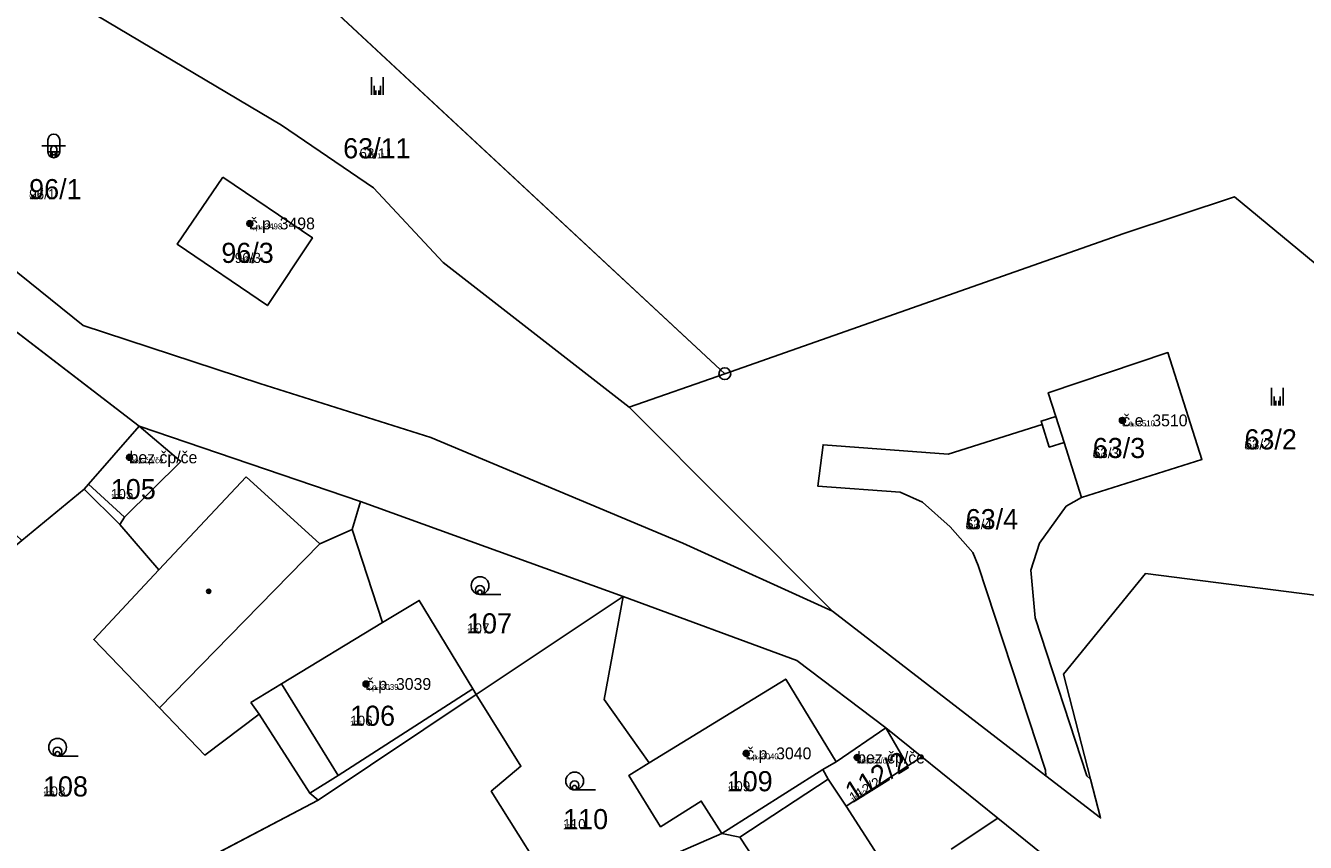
# Model space of a CAD drawing. Extents: x -759873 to -758487, y -975024 to -973516.
# Drawn here: x -759433 to -759325, y -974277 to -974208 of the extents above; entities that cross this region are included whole.
import ezdxf

# ---------------------------------------------------------------- set-up
doc = ezdxf.new("R2010")
doc.units = 0
for name, color, linetype in [('KAT_02_hranice parcel', 7, 'Continuous'), ('KAT_03_1000_st čísla parcelní', 7, 'Continuous'), ('KAT_03_1000_čísla parcelní', 7, 'Continuous'), ('KAT_03_1000_čísla popisná', 7, 'Continuous'), ('KAT_03_250_st čísla parcelní', 7, 'Continuous'), ('KAT_03_250_čísla parcelní', 7, 'Continuous'), ('KAT_03_250_čísla popisná', 7, 'Continuous'), ('KAT_03_500_st čísla parcelní', 7, 'Continuous'), ('KAT_03_500_čísla parcelní', 7, 'Continuous'), ('KAT_03_500_čísla popisná', 7, 'Continuous'), ('KAT_04_vnitřní kresba', 7, 'Continuous'), ('KAT_05_1000_značky kultur', 7, 'Continuous'), ('KAT_05_250_značky kultur', 7, 'Continuous'), ('KAT_05_500_značky kultur', 7, 'Continuous'), ('KAT_07_1000_značky budov', 7, 'Continuous'), ('KAT_07_250_značky budov', 7, 'Continuous'), ('KAT_07_500_značky budov', 7, 'Continuous'), ('KAT_11_značky bodu BP', 7, 'Continuous'), ('KAT_14_plocha_budovy', 7, 'Continuous'), ('KAT_14_plocha_pozemek', 7, 'Continuous')]:
    doc.layers.add(name, color=color, linetype=linetype)

msp = doc.modelspace()

# ---------------------------------------------------------------- linework, layer by layer
at = {"layer": 'KAT_02_hranice parcel'}
for p, q in [((-759416.57, -974197.82), (-759373.99, -974237.42)), ((-759453.16, -974219.06), (-759423.45, -974241.84)), ((-759373.99, -974237.42), (-759382.06, -974240.25)), ((-759382.06, -974240.25), (-759364.9, -974257.48)), ((-759423.45, -974241.84), (-759404.76, -974248.21)), ((-759433.37, -974251.51), (-759428.09, -974247.17)), ((-759428.09, -974247.17), (-759425.09, -974250.16)), ((-759404.76, -974248.21), (-759382.57, -974256.23)), ((-759394.98, -974264.51), (-759382.57, -974256.23)), ((-759364.9, -974257.48), (-759346.87, -974271.37)), ((-759408.33, -974273.42), (-759394.98, -974264.51)), ((-759360.4, -974267.32), (-759357.36, -974269.77)), ((-759374.24, -974276.25), (-759365.72, -974270.85)), ((-759427.48, -974283.47), (-759408.33, -974273.42))]:
    msp.add_line(p, q, dxfattribs=at)
for points in [[(-759382.06, -974240.25), (-759397.78, -974228.02), (-759403.67, -974221.73), (-759411.44, -974216.42), (-759427.02, -974207.16), (-759417.13, -974198.96), (-759416.57, -974197.82)], [(-759364.9, -974257.48), (-759377.53, -974251.74), (-759398.81, -974242.81), (-759413.25, -974238.25), (-759428.19, -974233.35), (-759448.25, -974217.2)], [(-759416.37, -974220.83), (-759408.82, -974225.94), (-759412.62, -974231.67), (-759420.24, -974226.48), (-759416.37, -974220.83)], [(-759373.99, -974237.42), (-759340.28, -974225.59), (-759330.94, -974222.47), (-759318.77, -974232.53)], [(-759347.19, -974241.71), (-759347.28, -974241.42), (-759346.03, -974241.02), (-759346.67, -974239.02), (-759336.57, -974235.63), (-759333.7, -974244.65), (-759343.86, -974247.88)], [(-759346.87, -974271.37), (-759346.89, -974270.91), (-759352.58, -974253.61), (-759353.05, -974252.52), (-759354.95, -974250.36), (-759357.28, -974248.27), (-759359.17, -974247.42), (-759366.12, -974246.92), (-759365.69, -974243.42), (-759355.13, -974244.22), (-759347.19, -974241.71)], [(-759347.19, -974241.71), (-759346.59, -974243.62), (-759345.34, -974243.22), (-759343.86, -974247.88)], [(-759428.09, -974247.17), (-759427.72, -974246.75), (-759423.45, -974241.84)], [(-759425.09, -974250.16), (-759424.69, -974249.54), (-759419.94, -974244.83), (-759423.45, -974241.84)], [(-759394.98, -974264.51), (-759395.28, -974264.04), (-759399.79, -974256.56), (-759402.91, -974258.44), (-759405.47, -974250.58), (-759404.76, -974248.21)], [(-759343.86, -974247.88), (-759345.17, -974248.61), (-759347.41, -974251.72), (-759348.14, -974254.02), (-759347.78, -974258.04), (-759343.41, -974271.37), (-759343.09, -974271.67)], [(-759425.09, -974250.16), (-759421.79, -974253.98), (-759427.28, -974259.86), (-759421.73, -974265.62), (-759417.89, -974269.62), (-759413.32, -974266.17), (-759409.03, -974272.84), (-759408.33, -974273.42)], [(-759343.09, -974271.67), (-759345.37, -974262.78), (-759338.47, -974254.29), (-759324.16, -974256.13), (-759317.89, -974266.22), (-759318.14, -974285.7), (-759311.79, -974294.78), (-759308.64, -974296.79)], [(-759382.57, -974256.23), (-759384.18, -974264.92), (-759380.39, -974270.29), (-759382.09, -974271.34), (-759379.41, -974275.68), (-759375.98, -974273.51), (-759374.24, -974276.25)], [(-759382.57, -974256.23), (-759367.9, -974261.65), (-759360.4, -974267.32)], [(-759394.98, -974264.51), (-759391.21, -974270.57), (-759393.71, -974272.68), (-759387.77, -974282.14)], [(-759365.72, -974270.85), (-759364.59, -974270.19), (-759360.4, -974267.32)], [(-759357.36, -974269.77), (-759358.53, -974270.53), (-759363.73, -974273.94), (-759365.27, -974271.66), (-759365.72, -974270.85)], [(-759357.36, -974269.77), (-759350.93, -974274.95), (-759343.18, -974281.19)], [(-759346.87, -974271.37), (-759342.25, -974274.93), (-759343.09, -974271.67)], [(-759387.77, -974282.14), (-759384.06, -974280.53), (-759374.24, -974276.25)], [(-759374.24, -974276.25), (-759372.72, -974276.55), (-759368.52, -974282.94), (-759375.24, -974287.36), (-759370.69, -974296.74)]]:
    msp.add_lwpolyline(points, dxfattribs=at)
at = {"layer": 'KAT_03_1000_čísla popisná'}
for centre in [(-759414.11, -974224.73), (-759340.41, -974241.36), (-759424.26, -974244.48), (-759404.29, -974263.62), (-759372.18, -974269.48), (-759362.81, -974269.83)]:
    msp.add_circle(centre, 0.25, dxfattribs=at)
at = {"layer": 'KAT_03_250_čísla popisná'}
for centre in [(-759414.11, -974224.73), (-759340.41, -974241.36), (-759424.26, -974244.48), (-759404.29, -974263.62), (-759372.18, -974269.48), (-759362.81, -974269.83)]:
    msp.add_circle(centre, 0.0625, dxfattribs=at)
at = {"layer": 'KAT_03_500_čísla popisná'}
for centre in [(-759414.11, -974224.73), (-759340.41, -974241.36), (-759424.26, -974244.48), (-759404.29, -974263.62), (-759372.18, -974269.48), (-759362.81, -974269.83)]:
    msp.add_circle(centre, 0.125, dxfattribs=at)
at = {"layer": 'KAT_04_vnitřní kresba'}
for p, q in [((-759346.03, -974241.02), (-759345.34, -974243.22)), ((-759421.79, -974253.98), (-759414.4, -974246.13)), ((-759414.4, -974246.13), (-759408.18, -974251.78)), ((-759427.72, -974246.75), (-759424.69, -974249.54)), ((-759408.18, -974251.78), (-759405.47, -974250.58)), ((-759415.83, -974259.59), (-759408.18, -974251.78)), ((-759411.42, -974263.6), (-759402.91, -974258.44)), ((-759421.73, -974265.62), (-759415.83, -974259.59)), ((-759380.39, -974270.29), (-759368.84, -974263.21)), ((-759368.84, -974263.21), (-759364.59, -974270.19)), ((-759414.01, -974265.17), (-759411.42, -974263.6)), ((-759411.42, -974263.6), (-759406.64, -974271.34)), ((-759406.64, -974271.34), (-759395.28, -974264.04)), ((-759414.01, -974265.17), (-759413.32, -974266.17)), ((-759360.4, -974267.32), (-759358.53, -974270.53)), ((-759409.03, -974272.84), (-759406.64, -974271.34)), ((-759372.72, -974276.55), (-759365.27, -974271.66)), ((-759363.73, -974273.94), (-759361.08, -974278.05)), ((-759354.87, -974277.58), (-759350.93, -974274.95))]:
    msp.add_line(p, q, dxfattribs=at)
at = {"layer": 'KAT_05_1000_značky kultur'}
for p, q in [((-759403.84, -974213.87), (-759403.84, -974212.37)), ((-759402.84, -974213.87), (-759402.84, -974212.37)), ((-759431.16, -974217.68), (-759431.16, -974218.68)), ((-759430.16, -974218.68), (-759430.16, -974217.68)), ((-759431.66, -974218.18), (-759429.66, -974218.18)), ((-759327.83, -974240.1), (-759327.83, -974238.6)), ((-759326.83, -974240.1), (-759326.83, -974238.6)), ((-759394.66, -974256.06), (-759392.91, -974256.06)), ((-759430.34, -974269.71), (-759428.59, -974269.71)), ((-759386.67, -974272.56), (-759384.92, -974272.56))]:
    msp.add_line(p, q, dxfattribs=at)
for centre in [(-759394.66, -974255.31), (-759430.34, -974268.96), (-759386.67, -974271.81)]:
    msp.add_circle(centre, 0.75, dxfattribs=at)
for centre, start, end in [((-759430.66, -974217.68), 0, 180), ((-759430.66, -974218.68), 180, 359.9879)]:
    msp.add_arc(centre, 0.5, start, end, dxfattribs=at)
at = {"layer": 'KAT_05_250_značky kultur'}
for p, q in [((-759403.46, -974213.87), (-759403.46, -974213.49)), ((-759403.21, -974213.87), (-759403.21, -974213.49)), ((-759430.91, -974218.93), (-759430.41, -974218.93)), ((-759430.79, -974218.81), (-759430.79, -974219.06)), ((-759430.53, -974219.06), (-759430.53, -974218.81)), ((-759327.45, -974240.1), (-759327.45, -974239.72)), ((-759327.2, -974240.1), (-759327.2, -974239.72)), ((-759394.67, -974256.06), (-759394.23, -974256.06)), ((-759430.35, -974269.71), (-759429.91, -974269.71)), ((-759386.68, -974272.56), (-759386.24, -974272.56))]:
    msp.add_line(p, q, dxfattribs=at)
for centre in [(-759394.67, -974255.87), (-759430.35, -974269.52), (-759386.68, -974272.37)]:
    msp.add_circle(centre, 0.187, dxfattribs=at)
for centre, start, end in [((-759430.66, -974218.81), 0, 180), ((-759430.66, -974219.06), 180, 359.9879)]:
    msp.add_arc(centre, 0.125, start, end, dxfattribs=at)
at = {"layer": 'KAT_05_500_značky kultur'}
for p, q in [((-759403.59, -974213.87), (-759403.59, -974213.12)), ((-759403.08, -974213.87), (-759403.08, -974213.12)), ((-759431.16, -974218.68), (-759430.16, -974218.68)), ((-759430.91, -974218.43), (-759430.91, -974218.93)), ((-759430.41, -974218.93), (-759430.41, -974218.43)), ((-759327.58, -974240.1), (-759327.58, -974239.35)), ((-759327.08, -974240.1), (-759327.08, -974239.35)), ((-759394.67, -974256.06), (-759393.79, -974256.06)), ((-759430.35, -974269.71), (-759429.47, -974269.71)), ((-759386.68, -974272.56), (-759385.8, -974272.56))]:
    msp.add_line(p, q, dxfattribs=at)
for centre in [(-759394.67, -974255.68), (-759430.35, -974269.33), (-759386.68, -974272.18)]:
    msp.add_circle(centre, 0.375, dxfattribs=at)
for centre, start, end in [((-759430.66, -974218.43), 0, 180), ((-759430.66, -974218.93), 180, 359.9879)]:
    msp.add_arc(centre, 0.25, start, end, dxfattribs=at)
at = {"layer": 'KAT_07_1000_značky budov'}
for centre in [(-759414.12, -974224.73), (-759340.42, -974241.36), (-759424.27, -974244.48), (-759417.58, -974255.8), (-759404.3, -974263.62), (-759372.19, -974269.48), (-759362.82, -974269.83)]:
    msp.add_circle(centre, 0.175, dxfattribs=at)
at = {"layer": 'KAT_07_250_značky budov'}
for centre in [(-759414.11, -974224.73), (-759340.41, -974241.36), (-759424.26, -974244.48), (-759417.57, -974255.8), (-759404.29, -974263.62), (-759372.18, -974269.48), (-759362.81, -974269.83)]:
    msp.add_circle(centre, 0.0437, dxfattribs=at)
at = {"layer": 'KAT_07_500_značky budov'}
for centre in [(-759414.11, -974224.73), (-759340.41, -974241.36), (-759424.26, -974244.48), (-759417.57, -974255.8), (-759404.29, -974263.62), (-759372.18, -974269.48), (-759362.81, -974269.83)]:
    msp.add_circle(centre, 0.0875, dxfattribs=at)
at = {"layer": 'KAT_11_značky bodu BP'}
for radius in [0.5, 0.0303]:
    msp.add_circle((-759373.99, -974237.42), radius, dxfattribs=at)
at = {"layer": 'KAT_14_plocha_budovy'}
for points in [[(-759416.37, -974220.83), (-759420.24, -974226.48), (-759412.62, -974231.67), (-759408.82, -974225.94)], [(-759336.57, -974235.63), (-759346.67, -974239.02), (-759346.03, -974241.02), (-759345.34, -974243.22), (-759343.86, -974247.88), (-759333.7, -974244.65)], [(-759427.72, -974246.75), (-759424.69, -974249.54), (-759419.94, -974244.83), (-759423.45, -974241.84)], [(-759411.42, -974263.6), (-759406.64, -974271.34), (-759395.28, -974264.04), (-759399.79, -974256.56), (-759402.91, -974258.44)], [(-759382.09, -974271.34), (-759379.41, -974275.68), (-759375.98, -974273.51), (-759374.24, -974276.25), (-759365.72, -974270.85), (-759364.59, -974270.19), (-759368.84, -974263.21), (-759380.39, -974270.29)], [(-759363.73, -974273.94), (-759358.53, -974270.53), (-759360.4, -974267.32), (-759364.59, -974270.19), (-759365.72, -974270.85), (-759365.27, -974271.66)]]:
    msp.add_lwpolyline(points, close=True, dxfattribs=at)
at = {"layer": 'KAT_14_plocha_pozemek'}
for points in [[(-759397.78, -974228.02), (-759403.67, -974221.73), (-759411.44, -974216.42), (-759427.02, -974207.16), (-759417.13, -974198.96), (-759416.57, -974197.82), (-759409.11, -974182.46), (-759411.13, -974183.35), (-759411.55, -974185.84), (-759421.6, -974198.71), (-759430.32, -974203.35), (-759439.36, -974211.8), (-759441.1, -974209.74), (-759448.25, -974217.2), (-759428.19, -974233.35), (-759413.25, -974238.25), (-759398.81, -974242.81), (-759377.53, -974251.74), (-759364.9, -974257.48), (-759382.06, -974240.25)], [(-759373.99, -974237.42), (-759416.57, -974197.82), (-759417.13, -974198.96), (-759427.02, -974207.16), (-759411.44, -974216.42), (-759403.67, -974221.73), (-759397.78, -974228.02), (-759382.06, -974240.25)], [(-759428.09, -974247.17), (-759427.72, -974246.75), (-759423.45, -974241.84), (-759453.16, -974219.06), (-759463.77, -974223.21), (-759457.41, -974236.54), (-759459.8, -974239.06), (-759447, -974252), (-759442.74, -974247.8), (-759440.09, -974245.19), (-759433.37, -974251.51)], [(-759416.37, -974220.83), (-759408.82, -974225.94), (-759412.62, -974231.67), (-759420.24, -974226.48)], [(-759416.37, -974220.83), (-759420.24, -974226.48), (-759412.62, -974231.67), (-759408.82, -974225.94)], [(-759343.86, -974247.88), (-759333.7, -974244.65), (-759336.57, -974235.63), (-759346.67, -974239.02), (-759346.03, -974241.02), (-759347.28, -974241.42), (-759347.19, -974241.71), (-759346.59, -974243.62), (-759345.34, -974243.22)], [(-759342.25, -974274.93), (-759343.09, -974271.67), (-759343.41, -974271.37), (-759347.78, -974258.04), (-759348.14, -974254.02), (-759347.41, -974251.72), (-759345.17, -974248.61), (-759343.86, -974247.88), (-759345.34, -974243.22), (-759346.59, -974243.62), (-759347.19, -974241.71), (-759355.13, -974244.22), (-759365.69, -974243.42), (-759366.12, -974246.92), (-759359.17, -974247.42), (-759357.28, -974248.27), (-759354.95, -974250.36), (-759353.05, -974252.52), (-759352.58, -974253.61), (-759346.89, -974270.91), (-759346.87, -974271.37)], [(-759419.94, -974244.83), (-759423.45, -974241.84), (-759427.72, -974246.75), (-759428.09, -974247.17), (-759425.09, -974250.16), (-759424.69, -974249.54)], [(-759394.98, -974264.51), (-759395.28, -974264.04), (-759399.79, -974256.56), (-759402.91, -974258.44), (-759405.47, -974250.58), (-759404.76, -974248.21), (-759423.45, -974241.84), (-759419.94, -974244.83), (-759424.69, -974249.54), (-759425.09, -974250.16), (-759421.79, -974253.98), (-759427.28, -974259.86), (-759421.73, -974265.62), (-759417.89, -974269.62), (-759413.32, -974266.17), (-759409.03, -974272.84), (-759408.33, -974273.42)], [(-759430.3, -974282.17), (-759427.48, -974283.47), (-759408.33, -974273.42), (-759409.03, -974272.84), (-759413.32, -974266.17), (-759417.89, -974269.62), (-759421.73, -974265.62), (-759427.28, -974259.86), (-759421.79, -974253.98), (-759425.09, -974250.16), (-759428.09, -974247.17), (-759433.37, -974251.51), (-759448.76, -974264.33)], [(-759382.57, -974256.23), (-759404.76, -974248.21), (-759405.47, -974250.58), (-759402.91, -974258.44), (-759399.79, -974256.56), (-759395.28, -974264.04), (-759394.98, -974264.51)], [(-759391.21, -974270.57), (-759393.71, -974272.68), (-759387.77, -974282.14), (-759384.06, -974280.53), (-759374.24, -974276.25), (-759375.98, -974273.51), (-759379.41, -974275.68), (-759382.09, -974271.34), (-759380.39, -974270.29), (-759384.18, -974264.92), (-759382.57, -974256.23), (-759394.98, -974264.51)], [(-759380.39, -974270.29), (-759382.09, -974271.34), (-759379.41, -974275.68), (-759375.98, -974273.51), (-759374.24, -974276.25), (-759365.72, -974270.85), (-759364.59, -974270.19), (-759360.4, -974267.32), (-759367.9, -974261.65), (-759382.57, -974256.23), (-759384.18, -974264.92)], [(-759387.77, -974282.14), (-759393.71, -974272.68), (-759391.21, -974270.57), (-759394.98, -974264.51), (-759408.33, -974273.42), (-759427.48, -974283.47), (-759417.12, -974295.3), (-759410.1, -974291.79)], [(-759357.36, -974269.77), (-759360.4, -974267.32), (-759364.59, -974270.19), (-759365.72, -974270.85), (-759365.27, -974271.66), (-759363.73, -974273.94), (-759358.53, -974270.53)], [(-759343.18, -974281.19), (-759350.93, -974274.95), (-759357.36, -974269.77), (-759358.53, -974270.53), (-759363.73, -974273.94), (-759365.27, -974271.66), (-759365.72, -974270.85), (-759374.24, -974276.25), (-759372.72, -974276.55), (-759368.52, -974282.94), (-759375.24, -974287.36), (-759370.69, -974296.74), (-759358.13, -974291.06)], [(-759400.45, -974314.69), (-759385.51, -974304.02), (-759379.45, -974301.04), (-759370.69, -974296.74), (-759375.24, -974287.36), (-759368.52, -974282.94), (-759372.72, -974276.55), (-759374.24, -974276.25), (-759384.06, -974280.53), (-759387.77, -974282.14), (-759410.1, -974291.79), (-759417.12, -974295.3)]]:
    msp.add_lwpolyline(points, close=True, dxfattribs=at)
for points in [[(-759416.57, -974197.82), (-759373.99, -974237.42), (-759340.28, -974225.59), (-759330.94, -974222.47), (-759318.77, -974232.53), (-759320.51, -974218.98), (-759300.41, -974213.17), (-759299.7, -974212.97), (-759291.14, -974210.49), (-759293.96, -974197.53)], [(-759324.16, -974256.13), (-759338.47, -974254.29), (-759345.37, -974262.78), (-759343.09, -974271.67), (-759342.25, -974274.93), (-759346.87, -974271.37), (-759364.9, -974257.48), (-759377.53, -974251.74), (-759398.81, -974242.81), (-759413.25, -974238.25), (-759428.19, -974233.35), (-759448.25, -974217.2)], [(-759453.16, -974219.06), (-759423.45, -974241.84), (-759404.76, -974248.21), (-759382.57, -974256.23), (-759367.9, -974261.65), (-759360.4, -974267.32), (-759357.36, -974269.77), (-759350.93, -974274.95), (-759343.18, -974281.19), (-759336.89, -974286.48), (-759336.26, -974287.05), (-759332.18, -974290.8), (-759329.53, -974293.23), (-759315.21, -974301.29)], [(-759318.77, -974232.53), (-759330.94, -974222.47), (-759340.28, -974225.59), (-759373.99, -974237.42), (-759382.06, -974240.25), (-759364.9, -974257.48), (-759346.87, -974271.37), (-759346.89, -974270.91), (-759352.58, -974253.61), (-759353.05, -974252.52), (-759354.95, -974250.36), (-759357.28, -974248.27), (-759359.17, -974247.42), (-759366.12, -974246.92), (-759365.69, -974243.42), (-759355.13, -974244.22), (-759347.19, -974241.71), (-759347.28, -974241.42), (-759346.03, -974241.02), (-759346.67, -974239.02), (-759336.57, -974235.63), (-759333.7, -974244.65), (-759343.86, -974247.88), (-759345.17, -974248.61), (-759347.41, -974251.72), (-759348.14, -974254.02), (-759347.78, -974258.04), (-759343.41, -974271.37), (-759343.09, -974271.67), (-759345.37, -974262.78), (-759338.47, -974254.29), (-759324.16, -974256.13)]]:
    msp.add_lwpolyline(points, dxfattribs=at)

# ---------------------------------------------------------------- texts
at = {"layer": 'KAT_03_1000_st čísla parcelní'}
for s, p in [('96/3', (-759416.51, -974228.06)), ('63/3', (-759342.91, -974244.54)), ('105', (-759425.84, -974248.01)), ('106', (-759405.63, -974267.15)), ('109', (-759373.74, -974272.68))]:
    msp.add_text(s, height=1.7, dxfattribs=at).set_placement(p)
msp.add_text('112/2', height=1.7, rotation=32, dxfattribs=at).set_placement((-759363.14, -974273.67))
at = {"layer": 'KAT_03_1000_čísla parcelní'}
for s, p in [('63/11', (-759406.22, -974219.23)), ('96/1', (-759432.74, -974222.68)), ('63/2', (-759330.1, -974243.81)), ('63/4', (-759353.64, -974250.55)), ('107', (-759395.76, -974259.35)), ('108', (-759431.57, -974273.12)), ('110', (-759387.64, -974275.88))]:
    msp.add_text(s, height=1.7, dxfattribs=at).set_placement(p)
at = {"layer": 'KAT_03_1000_čísla popisná'}
for s, p in [('č.p. 3498', (-759414.11, -974225.23)), ('č.e. 3510', (-759340.41, -974241.86)), ('bez čp/če', (-759424.26, -974244.98)), ('č.p. 3039', (-759404.29, -974264.12)), ('č.p. 3040', (-759372.18, -974269.98)), ('bez čp/če', (-759362.81, -974270.33))]:
    msp.add_text(s, height=1, dxfattribs=at).set_placement(p)
at = {"layer": 'KAT_03_250_st čísla parcelní'}
for s, p in [('96/3', (-759414.82, -974228.06)), ('63/3', (-759342.91, -974244.54)), ('105', (-759425.84, -974248.01)), ('106', (-759405.63, -974267.15)), ('109', (-759373.74, -974272.68))]:
    msp.add_text(s, height=0.425, dxfattribs=at).set_placement(p)
msp.add_text('112/2', height=0.425, rotation=32, dxfattribs=at).set_placement((-759363.14, -974273.67))
at = {"layer": 'KAT_03_250_čísla parcelní'}
for s, p in [('63/11', (-759404.16, -974219.23)), ('96/1', (-759432.74, -974222.68)), ('63/2', (-759330.1, -974243.81)), ('63/4', (-759353.64, -974250.55)), ('107', (-759395.76, -974259.35)), ('108', (-759431.57, -974273.12)), ('110', (-759387.64, -974275.88))]:
    msp.add_text(s, height=0.425, dxfattribs=at).set_placement(p)
at = {"layer": 'KAT_03_250_čísla popisná'}
for s, p in [('č.p. 3498', (-759414.11, -974225.23)), ('č.e. 3510', (-759340.41, -974241.86)), ('bez čp/če', (-759424.26, -974244.98)), ('č.p. 3039', (-759404.29, -974264.12)), ('č.p. 3040', (-759372.18, -974269.98)), ('bez čp/če', (-759362.81, -974270.33))]:
    msp.add_text(s, height=0.25, dxfattribs=at).set_placement(p)
at = {"layer": 'KAT_03_500_st čísla parcelní'}
for s, p in [('96/3', (-759415.38, -974228.06)), ('63/3', (-759342.91, -974244.54)), ('105', (-759425.84, -974248.01)), ('106', (-759405.63, -974267.15)), ('109', (-759373.74, -974272.68))]:
    msp.add_text(s, height=0.85, dxfattribs=at).set_placement(p)
msp.add_text('112/2', height=0.85, rotation=32, dxfattribs=at).set_placement((-759363.14, -974273.67))
at = {"layer": 'KAT_03_500_čísla parcelní'}
for s, p in [('63/11', (-759404.85, -974219.23)), ('96/1', (-759432.74, -974222.68)), ('63/2', (-759330.1, -974243.81)), ('63/4', (-759353.64, -974250.55)), ('107', (-759395.76, -974259.35)), ('108', (-759431.57, -974273.12)), ('110', (-759387.64, -974275.88))]:
    msp.add_text(s, height=0.85, dxfattribs=at).set_placement(p)
at = {"layer": 'KAT_03_500_čísla popisná'}
for s, p in [('č.p. 3498', (-759414.11, -974225.23)), ('č.e. 3510', (-759340.41, -974241.86)), ('bez čp/če', (-759424.26, -974244.98)), ('č.p. 3039', (-759404.29, -974264.12)), ('č.p. 3040', (-759372.18, -974269.98)), ('bez čp/če', (-759362.81, -974270.33))]:
    msp.add_text(s, height=0.5, dxfattribs=at).set_placement(p)

doc.saveas('drawing.dxf')
